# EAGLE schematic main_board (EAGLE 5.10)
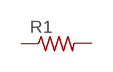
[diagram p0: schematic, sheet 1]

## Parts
R1  R-US_0207/10  [0207/10]
Unconnected: R1.1 R1.2

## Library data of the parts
R1 = rcl:R-US_: RESISTOR, American symbol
